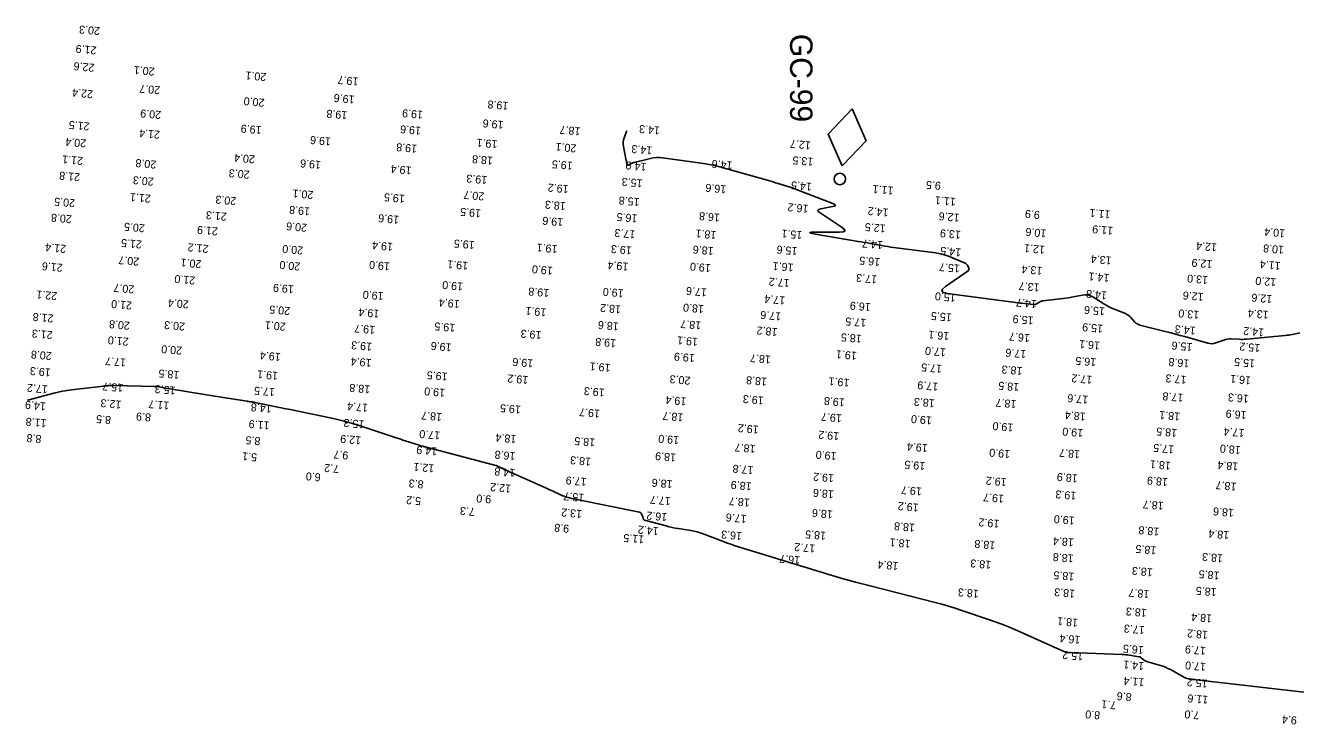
# Model space of a CAD drawing. Extents: x 988130 to 1132882, y 654656 to 841453.
# Drawn here: x 1034184 to 1034978, y 779238 to 779675 of the extents above; entities that cross this region are included whole.
import ezdxf

# ---------------------------------------------------------------- set-up
doc = ezdxf.new("R2010")
doc.units = 0
for name, color, linetype in [('V-CHAN-NAID', 7, 'Continuous'), ('V-TOPO-MAJR', 7, 'Continuous'), ('V-TOPO-SOUN', 7, 'Continuous')]:
    doc.layers.add(name, color=color, linetype=linetype)

msp = doc.modelspace()

# ---------------------------------------------------------------- linework, layer by layer
at = {"layer": 'V-CHAN-NAID'}
msp.add_lwpolyline([(1034694.48, 779587.38), (1034709.42, 779603.03), (1034700.73, 779622.84), (1034685.79, 779607.19)], close=True, dxfattribs=at)
msp.add_circle((1034693.02, 779579.11), 3.6, dxfattribs=at)
at = {"layer": 'V-TOPO-MAJR'}
for points in [[(1034980.42, 779482.99), (1034975.9, 779482.08), (1034974.76, 779481.86), (1034973.62, 779481.68), (1034972.48, 779481.53), (1034971.33, 779481.4), (1034947.13, 779479.11), (1034945.95, 779479.01), (1034944.77, 779478.97), (1034943.59, 779478.96), (1034942.41, 779479), (1034937.69, 779479.23), (1034936.52, 779479.23), (1034935.36, 779479.12), (1034934.22, 779478.89), (1034933.1, 779478.54), (1034928.03, 779476.71), (1034926.81, 779476.37), (1034925.58, 779476.23), (1034924.35, 779476.28), (1034923.11, 779476.54), (1034908.55, 779480.67), (1034905.71, 779481.46), (1034902.86, 779482.23), (1034900, 779482.98), (1034897.14, 779483.71), (1034880.57, 779487.84), (1034879.65, 779488.14), (1034878.8, 779488.57), (1034878.03, 779489.12), (1034877.34, 779489.8), (1034874.72, 779492.78), (1034874.03, 779493.48), (1034873.28, 779494.08), (1034872.46, 779494.59), (1034871.58, 779495.01), (1034863.98, 779498.07), (1034862.42, 779498.74), (1034860.9, 779499.47), (1034859.42, 779500.28), (1034857.97, 779501.15), (1034851.2, 779505.43), (1034849.68, 779506.21), (1034848.09, 779506.67), (1034846.45, 779506.81), (1034844.75, 779506.62), (1034837.81, 779505.24), (1034836.08, 779504.91), (1034834.33, 779504.62), (1034832.59, 779504.38), (1034830.83, 779504.17), (1034819.98, 779502.99), (1034819.43, 779502.9), (1034818.9, 779502.76), (1034818.39, 779502.55), (1034817.91, 779502.29), (1034815.99, 779501.13), (1034815.5, 779500.88), (1034815, 779500.73), (1034814.47, 779500.66), (1034813.92, 779500.68), (1034806.89, 779501.5), (1034805.53, 779501.66), (1034804.17, 779501.83), (1034802.82, 779502), (1034801.46, 779502.17), (1034760.12, 779507.57), (1034757.78, 779508.13), (1034756.82, 779509.04), (1034757.25, 779510.29), (1034759.06, 779511.88), (1034773.22, 779521.83), (1034773.55, 779522.15), (1034773.74, 779522.51), (1034773.76, 779522.91), (1034773.62, 779523.35), (1034772.75, 779525.21), (1034772.5, 779525.64), (1034772.19, 779526), (1034771.81, 779526.3), (1034771.37, 779526.53), (1034760.89, 779530.88), (1034758.97, 779531.6), (1034757.01, 779532.19), (1034755.02, 779532.65), (1034752.99, 779532.98), (1034726.66, 779536.37), (1034724.81, 779536.62), (1034722.96, 779536.89), (1034721.12, 779537.18), (1034719.28, 779537.5), (1034711.92, 779538.82), (1034710.08, 779539.15), (1034708.24, 779539.47), (1034706.4, 779539.79), (1034704.56, 779540.11), (1034677.76, 779544.7), (1034675.14, 779545.22), (1034674.28, 779545.59), (1034675.19, 779545.81), (1034677.87, 779545.87), (1034692.78, 779545.81), (1034695.26, 779546.01), (1034696.27, 779546.67), (1034695.79, 779547.76), (1034693.83, 779549.3), (1034680.71, 779557.89), (1034679.6, 779558.8), (1034679.31, 779559.55), (1034679.86, 779560.12), (1034681.24, 779560.53), (1034688.43, 779561.83), (1034689.79, 779562.19), (1034690.27, 779562.64), (1034689.88, 779563.18), (1034688.62, 779563.8), (1034666.49, 779572.43), (1034665.01, 779572.99), (1034663.52, 779573.52), (1034662.02, 779574.03), (1034660.52, 779574.5), (1034654.46, 779576.33), (1034652.95, 779576.79), (1034651.43, 779577.24), (1034649.92, 779577.68), (1034648.4, 779578.11), (1034622.35, 779585.52), (1034618.05, 779586.66), (1034613.72, 779587.66), (1034609.35, 779588.5), (1034604.96, 779589.19), (1034582.27, 779592.37), (1034580.39, 779592.55), (1034578.51, 779592.54), (1034576.65, 779592.35), (1034574.79, 779591.98), (1034564.63, 779589.45), (1034564.16, 779589.32), (1034563.69, 779589.16), (1034563.24, 779588.98), (1034562.79, 779588.77), (1034560.72, 779587.76), (1034560.46, 779587.67), (1034560.26, 779587.7), (1034560.12, 779587.85), (1034560.04, 779588.11), (1034559.75, 779589.98), (1034559.75, 779590.01), (1034559.75, 779590.04), (1034559.76, 779590.07), (1034559.78, 779590.1), (1034559.86, 779590.2), (1034559.87, 779590.23), (1034559.88, 779590.25), (1034559.88, 779590.28), (1034559.86, 779590.31), (1034559.72, 779590.52), (1034559.69, 779590.57), (1034559.67, 779590.62), (1034559.65, 779590.67), (1034559.63, 779590.72), (1034557.85, 779599.42), (1034557.66, 779600.79), (1034557.67, 779602.14), (1034557.88, 779603.48), (1034558.29, 779604.8), (1034559.93, 779609.07)], [(1034982.92, 779258.59), (1034914.09, 779266.51), (1034913.83, 779266.54), (1034913.57, 779266.57), (1034913.31, 779266.6), (1034913.05, 779266.63), (1034912.01, 779266.76), (1034911.75, 779266.79), (1034911.5, 779266.84), (1034911.24, 779266.9), (1034910.99, 779266.96), (1034909.91, 779267.27), (1034909.65, 779267.35), (1034909.4, 779267.45), (1034909.15, 779267.56), (1034908.91, 779267.68), (1034899.58, 779272.77), (1034898.09, 779273.53), (1034896.56, 779274.21), (1034895, 779274.81), (1034893.41, 779275.32), (1034884.64, 779277.91), (1034884.2, 779278.06), (1034883.79, 779278.26), (1034883.4, 779278.5), (1034883.03, 779278.78), (1034881.61, 779279.98), (1034881.24, 779280.25), (1034880.84, 779280.47), (1034880.42, 779280.63), (1034879.97, 779280.73), (1034873.98, 779281.71), (1034872.82, 779281.88), (1034871.67, 779282.01), (1034870.51, 779282.11), (1034869.34, 779282.17), (1034842.23, 779283.19), (1034841.42, 779283.22), (1034840.61, 779283.25), (1034839.8, 779283.28), (1034838.99, 779283.31), (1034835.75, 779283.44), (1034834.94, 779283.51), (1034834.16, 779283.65), (1034833.39, 779283.87), (1034832.64, 779284.17), (1034802.38, 779297.7), (1034798.35, 779299.44), (1034794.28, 779301.09), (1034790.18, 779302.64), (1034786.03, 779304.1), (1034769.37, 779309.72), (1034765.2, 779311.08), (1034761, 779312.36), (1034756.78, 779313.57), (1034752.53, 779314.69), (1034711.09, 779325.24), (1034702.78, 779327.41), (1034694.5, 779329.69), (1034686.24, 779332.06), (1034678.02, 779334.54), (1034630.34, 779349.25), (1034627.66, 779350.1), (1034624.99, 779350.99), (1034622.34, 779351.93), (1034619.7, 779352.92), (1034607.62, 779357.54), (1034605.76, 779358.2), (1034603.87, 779358.76), (1034601.95, 779359.22), (1034600.01, 779359.57), (1034592.19, 779360.8), (1034590.24, 779361.13), (1034588.3, 779361.51), (1034586.37, 779361.95), (1034584.45, 779362.43), (1034571, 779365.98), (1034570.8, 779366.05), (1034570.64, 779366.17), (1034570.52, 779366.32), (1034570.44, 779366.52), (1034570.18, 779367.37), (1034570.12, 779367.59), (1034570.04, 779367.8), (1034569.96, 779368.01), (1034569.88, 779368.21), (1034569.06, 779370.12), (1034568.86, 779370.46), (1034568.6, 779370.74), (1034568.28, 779370.93), (1034567.9, 779371.05), (1034529.83, 779378.76), (1034529, 779378.93), (1034528.17, 779379.11), (1034527.34, 779379.29), (1034526.51, 779379.48), (1034523.2, 779380.23), (1034522.38, 779380.44), (1034521.57, 779380.69), (1034520.78, 779380.98), (1034520, 779381.31), (1034514.97, 779383.59), (1034513.87, 779384.09), (1034512.78, 779384.58), (1034511.68, 779385.08), (1034510.58, 779385.57), (1034490.05, 779394.76), (1034489.2, 779395.14), (1034488.36, 779395.52), (1034487.52, 779395.91), (1034486.68, 779396.29), (1034482.37, 779398.27), (1034482.01, 779398.44), (1034481.65, 779398.61), (1034481.29, 779398.78), (1034480.93, 779398.96), (1034479.5, 779399.66), (1034479.14, 779399.83), (1034478.77, 779399.98), (1034478.4, 779400.11), (1034478.01, 779400.22), (1034433.2, 779412.02), (1034432.89, 779412.1), (1034432.58, 779412.18), (1034432.27, 779412.26), (1034431.96, 779412.34), (1034430.72, 779412.66), (1034430.41, 779412.74), (1034430.1, 779412.83), (1034429.8, 779412.92), (1034429.49, 779413.01), (1034421.51, 779415.63), (1034420.07, 779416.09), (1034418.64, 779416.57), (1034417.21, 779417.04), (1034415.78, 779417.51), (1034392.64, 779425.21), (1034388.45, 779426.53), (1034384.21, 779427.73), (1034379.95, 779428.81), (1034375.65, 779429.76), (1034355.51, 779433.91), (1034352.64, 779434.5), (1034349.76, 779435.09), (1034346.88, 779435.68), (1034344, 779436.26), (1034327.53, 779439.61), (1034327.12, 779439.69), (1034326.72, 779439.75), (1034326.31, 779439.81), (1034325.9, 779439.86), (1034324.27, 779440.05), (1034323.86, 779440.1), (1034323.45, 779440.15), (1034323.05, 779440.21), (1034322.64, 779440.27), (1034307.78, 779442.7), (1034305.17, 779443.12), (1034302.55, 779443.54), (1034299.94, 779443.96), (1034297.33, 779444.38), (1034273.1, 779448.22), (1034272.41, 779448.34), (1034271.72, 779448.46), (1034271.02, 779448.59), (1034270.33, 779448.73), (1034267.58, 779449.3), (1034266.89, 779449.43), (1034266.19, 779449.52), (1034265.5, 779449.58), (1034264.8, 779449.61), (1034239.51, 779450.1), (1034239.17, 779450.11), (1034238.83, 779450.11), (1034238.49, 779450.11), (1034238.15, 779450.11), (1034236.75, 779450.11), (1034236.43, 779450.1), (1034236.11, 779450.09), (1034235.79, 779450.07), (1034235.47, 779450.05), (1034234.2, 779449.95), (1034233.88, 779449.92), (1034233.56, 779449.89), (1034233.24, 779449.86), (1034232.93, 779449.82), (1034212.93, 779447.51), (1034210.14, 779447.13), (1034207.37, 779446.65), (1034204.62, 779446.07), (1034201.89, 779445.39), (1034185.64, 779441.01), (1034185.61, 779441.01), (1034185.58, 779441.02), (1034185.57, 779441.04), (1034185.57, 779441.07), (1034185.58, 779441.33)]]:
    msp.add_lwpolyline(points, dxfattribs=at)

# ---------------------------------------------------------------- texts
at = {"layer": 'V-CHAN-NAID'}
msp.add_text('GC-99', height=14, rotation=270, dxfattribs=at).set_placement((1034661.97, 779669.73))
at = {"layer": 'V-TOPO-SOUN'}
for s, p in [('20.3 ', (1034230.91, 779673.87)), ('21.9 ', (1034228.75, 779661.76)), ('22.6 ', (1034227.46, 779650.93)), ('20.1 ', (1034265.07, 779648.54)), ('20.1 ', (1034334.85, 779645.16)), ('20.7 ', (1034268.52, 779636.91)), ('19.7 ', (1034392.43, 779642.37)), ('22.4 ', (1034226.57, 779634.44)), ('20.0 ', (1034333.74, 779629.11)), ('19.6 ', (1034390.02, 779631.08)), ('19.8 ', (1034486.12, 779627.09)), ('20.9 ', (1034269.13, 779621.47)), ('19.8 ', (1034385.48, 779621.27)), ('19.9 ', (1034432.76, 779621.58)), ('21.5 ', (1034224.44, 779614.28)), ('19.9 ', (1034331.92, 779611.98)), ('19.6 ', (1034431.52, 779611.59)), ('19.6 ', (1034483.1, 779615.27)), ('18.7 ', (1034531.16, 779611.23)), ('14.3 ', (1034580.84, 779611.75)), ('20.4 ', (1034222.3, 779603.71)), ('21.4 ', (1034268.42, 779609.11)), ('19.6 ', (1034375.26, 779604.86)), ('19.1 ', (1034479.31, 779603.18)), ('19.8 ', (1034429.06, 779600.37)), ('20.1 ', (1034528.62, 779600.59)), ('14.3 ', (1034576.04, 779599.25)), ('12.7 ', (1034675.1, 779602.46)), ('21.1 ', (1034220.31, 779592.78)), ('20.8 ', (1034266.13, 779590.47)), ('20.4 ', (1034327.72, 779593.76)), ('19.6 ', (1034369.03, 779590.26)), ('18.8 ', (1034476.44, 779592.92)), ('19.5 ', (1034526.31, 779589.74)), ('14.9 ', (1034572.36, 779589.01)), ('14.6 ', (1034626.18, 779589.91)), ('13.5 ', (1034676.69, 779592.21)), ('21.8 ', (1034218.47, 779582.62)), ('20.3 ', (1034264.51, 779579.8)), ('20.3 ', (1034324.43, 779584.16)), ('19.4 ', (1034425.63, 779586.74)), ('19.3 ', (1034472.92, 779580.82)), ('20.1 ', (1034364.27, 779571.48)), ('19.2 ', (1034523.77, 779575.12)), ('15.3 ', (1034569.96, 779578.77)), ('16.6 ', (1034622.28, 779575.04)), ('14.5 ', (1034675.8, 779576.6)), ('11.1 ', (1034726.72, 779574.22)), ('9.5', (1034756.38, 779577.22)), ('20.5 ', (1034215.34, 779566.4)), ('21.1 ', (1034262.65, 779569.18)), ('20.3 ', (1034316.1, 779567.66)), ('19.5 ', (1034421.41, 779569.15)), ('20.7 ', (1034471.08, 779570.6)), ('18.3 ', (1034521.97, 779564.52)), ('15.8 ', (1034568.11, 779567.1)), ('11.1 ', (1034765.71, 779567.2)), ('20.8 ', (1034213.32, 779556.35)), ('21.3 ', (1034310.14, 779557.94)), ('19.8 ', (1034362.17, 779561.23)), ('19.6 ', (1034417.82, 779556.04)), ('19.5 ', (1034469.02, 779560.01)), ('16.5 ', (1034566.74, 779556.83)), ('16.8 ', (1034618.29, 779557.33)), ('16.2 ', (1034673.63, 779562.87)), ('14.2 ', (1034723.65, 779560.51)), ('12.6 ', (1034768.02, 779557.26)), ('9.9', (1034818.25, 779559.04)), ('11.1 ', (1034862.3, 779559.3)), ('20.5 ', (1034258.93, 779550.72)), ('21.9 ', (1034304.62, 779548.77)), ('20.6 ', (1034360.29, 779551.02)), ('19.6 ', (1034520.4, 779554.47)), ('12.5 ', (1034721.86, 779550.52)), ('10.6 ', (1034822.28, 779547.5)), ('11.9 ', (1034864, 779549.14)), ('10.4 ', (1034971.45, 779547.56)), ('21.5 ', (1034257.1, 779540.59)), ('19.5 ', (1034465.08, 779540.24)), ('17.3 ', (1034565.47, 779546.87)), ('18.1 ', (1034616.08, 779546.47)), ('15.1 ', (1034669.77, 779546.43)), ('14.7 ', (1034720.15, 779540.23)), ('13.9 ', (1034768.85, 779546.65)), ('21.4 ', (1034209.77, 779537.85)), ('21.2 ', (1034298.76, 779537.84)), ('20.0 ', (1034357.88, 779536.83)), ('19.4 ', (1034414.03, 779539.12)), ('19.1 ', (1034516.81, 779537.67)), ('19.3 ', (1034563.23, 779536.82)), ('18.6 ', (1034614.35, 779536.45)), ('15.6 ', (1034666.74, 779536.43)), ('14.5 ', (1034769.03, 779535.65)), ('12.1 ', (1034821.37, 779537.29)), ('12.4 ', (1034928.87, 779538.73)), ('10.8 ', (1034970.76, 779537.24)), ('21.6 ', (1034207.62, 779526.04)), ('20.7 ', (1034255.45, 779529.86)), ('20.1 ', (1034294.31, 779528.33)), ('20.0 ', (1034356.08, 779526.84)), ('19.0 ', (1034412.1, 779526.91)), ('19.1 ', (1034460.99, 779527.23)), ('19.0 ', (1034513.87, 779524.18)), ('19.4 ', (1034561.12, 779526.75)), ('19.0 ', (1034612.61, 779525.82)), ('16.1 ', (1034664.28, 779526.16)), ('16.5 ', (1034718.42, 779529.61)), ('15.7 ', (1034768.24, 779525.54)), ('13.4 ', (1034819.82, 779524.15)), ('13.4 ', (1034863.08, 779530.55)), ('12.9 ', (1034926.06, 779528.24)), ('11.4 ', (1034968.68, 779527.19)), ('21.0 ', (1034290.45, 779518.1)), ('17.2 ', (1034661.85, 779516.41)), ('17.3 ', (1034716.51, 779518.76)), ('14.1 ', (1034861.67, 779519.69)), ('13.0 ', (1034923.31, 779518.41)), ('12.0 ', (1034965.92, 779516.99)), ('22.1 ', (1034204.19, 779508.37)), ('20.7 ', (1034252.38, 779512.55)), ('19.9 ', (1034352.07, 779512.62)), ('19.0 ', (1034408.16, 779508.29)), ('19.0 ', (1034457.82, 779514.32)), ('19.8 ', (1034511.64, 779510.27)), ('19.0 ', (1034558.14, 779510.09)), ('17.6 ', (1034610.15, 779510.66)), ('13.7 ', (1034818.05, 779513.72)), ('14.8 ', (1034860.16, 779508.79)), ('12.6 ', (1034920.55, 779507.82)), ('21.0 ', (1034250.94, 779502.49)), ('20.4 ', (1034286.41, 779503.16)), ('19.4 ', (1034455.7, 779503.37)), ('18.2 ', (1034556.47, 779500.03)), ('18.0 ', (1034608.29, 779500.27)), ('17.4 ', (1034659.06, 779505.66)), ('16.9 ', (1034712.55, 779501.45)), ('15.0 ', (1034765.68, 779507.34)), ('14.7 ', (1034816.3, 779503.37)), ('12.6 ', (1034963.46, 779506.46)), ('21.8 ', (1034201.9, 779494.38)), ('20.5 ', (1034349.75, 779499.03)), ('19.4 ', (1034405.49, 779497.3)), ('19.1 ', (1034509.81, 779498.18)), ('17.6 ', (1034656.57, 779495.64)), ('15.5 ', (1034763.17, 779495.03)), ('15.9 ', (1034814.27, 779493.08)), ('15.6 ', (1034858.85, 779498.82)), ('13.0 ', (1034917.8, 779496.64)), ('13.4 ', (1034961.18, 779496.66)), ('21.3 ', (1034201.37, 779484.03)), ('20.8 ', (1034249.61, 779489.85)), ('20.3 ', (1034284.07, 779489.31)), ('20.1 ', (1034346.98, 779489.24)), ('19.7 ', (1034402.85, 779487.23)), ('19.5 ', (1034452.93, 779488.51)), ('19.3 ', (1034506.8, 779483.94)), ('18.6 ', (1034555.09, 779489.37)), ('18.7 ', (1034606.6, 779490)), ('18.2 ', (1034654.26, 779485.91)), ('17.5 ', (1034709.7, 779491.61)), ('15.9 ', (1034857.72, 779488)), ('14.3 ', (1034915.58, 779486.75)), ('14.2 ', (1034958.34, 779485.63)), ('21.0 ', (1034248.83, 779479.87)), ('19.3 ', (1034400.95, 779476.74)), ('19.6 ', (1034450.63, 779476.28)), ('19.8 ', (1034553.44, 779478.89)), ('19.1 ', (1034604.59, 779479.78)), ('18.5 ', (1034706.91, 779481.68)), ('16.1 ', (1034761.58, 779483.32)), ('16.7 ', (1034811.96, 779482.16)), ('16.1 ', (1034855.8, 779477.42)), ('15.6 ', (1034913.56, 779476.55)), ('15.2 ', (1034955.91, 779475.92)), ('20.8 ', (1034200.76, 779470.94)), ('20.0 ', (1034282.24, 779474.28)), ('19.4 ', (1034343.87, 779470.35)), ('19.9 ', (1034602.63, 779469.62)), ('18.7 ', (1034650.11, 779468.71)), ('19.1 ', (1034703.86, 779471.07)), ('17.0 ', (1034759.5, 779473.24)), ('17.6 ', (1034809.72, 779472.11)), ('19.3 ', (1034200.17, 779460.65)), ('17.7 ', (1034247.18, 779466.86)), ('19.4 ', (1034400.6, 779466.6)), ('19.6 ', (1034501.66, 779466.33)), ('19.1 ', (1034549.97, 779463.53)), ('17.5 ', (1034757.09, 779462.92)), ('18.3 ', (1034807.36, 779461.58)), ('16.5 ', (1034853.44, 779467.04)), ('16.8 ', (1034911.64, 779466.24)), ('15.5 ', (1034952.67, 779466.28)), ('18.5 ', (1034280.52, 779459.12)), ('19.1 ', (1034342.2, 779458.55)), ('19.5 ', (1034448.15, 779458.06)), ('19.2 ', (1034498.56, 779455.95)), ('20.3 ', (1034599.91, 779455.53)), ('18.8 ', (1034647.68, 779454.9)), ('19.1 ', (1034699.24, 779454.17)), ('17.2 ', (1034850.98, 779456.09)), ('17.3 ', (1034909.85, 779456.06)), ('16.1 ', (1034950.19, 779455.68)), ('17.2 ', (1034198.3, 779450.12)), ('15.7 ', (1034245.41, 779451.03)), ('15.3 ', (1034278.15, 779449.35)), ('17.5 ', (1034340.22, 779448.4)), ('18.8 ', (1034399.76, 779450.13)), ('19.0 ', (1034446.58, 779447.96)), ('19.3 ', (1034546.32, 779448.1)), ('17.9 ', (1034754.7, 779451.74)), ('18.5 ', (1034805.29, 779451.48)), ('17.8 ', (1034907.89, 779444.85)), ('16.3 ', (1034948.79, 779444.21)), ('14.9 ', (1034197.13, 779439.51)), ('12.3 ', (1034244.3, 779440.58)), ('11.7 ', (1034274.21, 779439.96)), ('14.8 ', (1034338.19, 779437.98)), ('17.4 ', (1034398.41, 779438.6)), ('19.5 ', (1034493.92, 779437.46)), ('19.4 ', (1034597.34, 779442.58)), ('19.3 ', (1034645.67, 779443.12)), ('19.8 ', (1034696.33, 779441.96)), ('18.3 ', (1034752.54, 779441.41)), ('18.7 ', (1034803.59, 779440.86)), ('17.6 ', (1034848.43, 779443.68)), ('11.8 ', (1034197.48, 779428.94)), ('8.5', (1034237.81, 779430.96)), ('8.9', (1034262.77, 779432.58)), ('15.3 ', (1034396.16, 779428.21)), ('18.7 ', (1034444.68, 779432.87)), ('19.7 ', (1034543.36, 779434.95)), ('18.7 ', (1034595.44, 779432.62)), ('19.7 ', (1034694.5, 779432.04)), ('19.0 ', (1034750.74, 779430.66)), ('18.4 ', (1034846.85, 779433.1)), ('18.1 ', (1034905.86, 779433.12)), ('16.9 ', (1034947.41, 779433.98)), ('11.9 ', (1034336.88, 779427.53)), ('17.0 ', (1034443.5, 779421.29)), ('19.2 ', (1034642.53, 779424.97)), ('19.2 ', (1034692.82, 779420.84)), ('19.0 ', (1034801.66, 779426.25)), ('19.0 ', (1034845.3, 779422.83)), ('18.5 ', (1034903.98, 779422.89)), ('17.4 ', (1034946.06, 779422.88)), ('8.8', (1034194.35, 779419.09)), ('8.5', (1034331.2, 779417.77)), ('12.9 ', (1034394.09, 779418.25)), ('18.4 ', (1034491.1, 779419.04)), ('18.5 ', (1034540.33, 779416.92)), ('19.0 ', (1034592.82, 779418.37)), ('18.7 ', (1034640.54, 779412.92)), ('19.4 ', (1034748.21, 779413.41)), ('17.5 ', (1034902.08, 779412.65)), ('5.1', (1034329.06, 779407.68)), ('9.7', (1034386.15, 779408.83)), ('14.9 ', (1034441.63, 779411.32)), ('16.8 ', (1034490.54, 779408.39)), ('18.3 ', (1034537.75, 779404.95)), ('18.9 ', (1034590.88, 779407.51)), ('19.0 ', (1034691.18, 779408.37)), ('19.0 ', (1034799.65, 779409.67)), ('18.7 ', (1034843.29, 779409.57)), ('18.0 ', (1034943.74, 779412.18)), ('7.2', (1034380.35, 779400.43)), ('12.1 ', (1034439.8, 779400.76)), ('14.8 ', (1034490.39, 779397.95)), ('17.8 ', (1034639.25, 779399.62)), ('19.5 ', (1034746.61, 779402.2)), ('18.1 ', (1034900.08, 779402.39)), ('18.4 ', (1034942.2, 779401.93)), ('6.0', (1034368.85, 779395.2)), ('8.3', (1034433.13, 779390.77)), ('17.9 ', (1034535.01, 779392.32)), ('18.6 ', (1034588.72, 779390.87)), ('18.9 ', (1034638.12, 779389.51)), ('19.2 ', (1034689.58, 779394.63)), ('19.2 ', (1034797.48, 779392.14)), ('18.9 ', (1034841.89, 779394.49)), ('18.9 ', (1034898.21, 779392.22)), ('18.7 ', (1034941.07, 779389.35)), ('9.0', (1034475.43, 779381.44)), ('12.2 ', (1034487.79, 779388.14)), ('15.7 ', (1034533.55, 779382.42)), ('18.6 ', (1034689.45, 779384.58)), ('19.7 ', (1034744.49, 779386.32)), ('19.7 ', (1034795.81, 779381.79)), ('19.3 ', (1034841.02, 779383.64)), ('5.2', (1034431.54, 779380.35)), ('7.3', (1034465.18, 779373.65)), ('17.7 ', (1034587.58, 779380.27)), ('18.7 ', (1034636.96, 779379.4)), ('19.2 ', (1034742.5, 779376.28)), ('18.7 ', (1034895.56, 779377.37)), ('18.6 ', (1034939.47, 779372.99)), ('13.2 ', (1034532.17, 779372.31)), ('16.2 ', (1034585.35, 779370.35)), ('17.6 ', (1034634.99, 779369.21)), ('18.6 ', (1034688.84, 779371.99)), ('19.2 ', (1034792.95, 779366.17)), ('19.0 ', (1034839.98, 779368.16)), ('9.8', (1034524.12, 779363.1)), ('14.2 ', (1034580.08, 779361.55)), ('16.3 ', (1034632.1, 779358.52)), ('18.5 ', (1034684.61, 779358.68)), ('18.8 ', (1034740.13, 779363.74)), ('18.8 ', (1034892.88, 779361.23)), ('18.4 ', (1034936.55, 779359.06)), ('11.5 ', (1034570.96, 779356.38)), ('17.2 ', (1034677.8, 779350.73)), ('18.1 ', (1034737.41, 779353.64)), ('18.8 ', (1034790.38, 779352.68)), ('18.4 ', (1034839.42, 779354.57)), ('18.5 ', (1034891.01, 779349.56)), ('16.7 ', (1034668.45, 779343.41)), ('18.8 ', (1034839.33, 779344.45)), ('18.3 ', (1034932.65, 779344.59)), ('18.4 ', (1034729.8, 779339.81)), ('18.3 ', (1034787.82, 779340.53)), ('18.5 ', (1034839.73, 779333.16)), ('18.3 ', (1034888.76, 779335.87)), ('18.5 ', (1034930.48, 779333.81)), ('18.3 ', (1034780.08, 779322.44)), ('18.3 ', (1034840.22, 779322.54)), ('18.7 ', (1034886.64, 779322.23)), ('18.5 ', (1034928.68, 779323.45)), ('18.3 ', (1034885, 779310.51)), ('18.1 ', (1034842.07, 779304.37)), ('18.4 ', (1034925.82, 779307.05)), ('16.4 ', (1034843.54, 779293.67)), ('17.3 ', (1034883.75, 779299.82)), ('18.2 ', (1034923.26, 779296.8)), ('16.5 ', (1034883.15, 779287.32)), ('17.9 ', (1034921.94, 779286.81)), ('15.2 ', (1034845.31, 779283.32)), ('14.1 ', (1034883.38, 779277.31)), ('17.0 ', (1034922, 779276.81)), ('11.4 ', (1034883.5, 779267.13)), ('15.2 ', (1034923.09, 779266.36)), ('8.6', (1034875.58, 779257.95)), ('11.6 ', (1034923.48, 779256.24)), ('8.0', (1034855.93, 779246.58)), ('7.1', (1034865.96, 779252.83)), ('7.0', (1034917.92, 779246.62)), ('9.4', (1034978.85, 779243.4))]:
    msp.add_text(s, height=5, rotation=175, dxfattribs=at).set_placement(p)

doc.saveas('drawing.dxf')
